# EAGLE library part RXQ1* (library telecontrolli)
RXQ1-433.9 Dual Band FM Transceiver Source: http://www.telecontrolli.com/pdf/transceivers/RXQ1.pdf
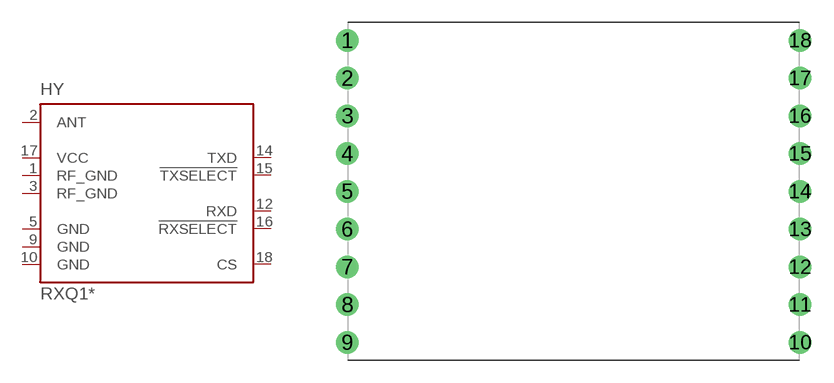
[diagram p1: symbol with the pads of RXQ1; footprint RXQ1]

Designator prefix HY

## RXQ1-433.9 (MPN: FM-RXQ1-433; OC_FARNELL: 1200988; OC_NEWARK: 96K9948)  [RXQ1]
1  RF_GND  pwr
2  ANT  in
3  RF_GND  pwr
5  GND  pwr
9  GND  pwr
10  GND  pwr
12  RXD  out
14  TXD  in
15  !TXSELECT  in
16  !RXSELECT  in
17  VCC  pwr
18  CS  in

## Footprint RXQ1 (pad centres in mm)
RXQ1-433.9 Dual Band FM Transceiver Source: http://www.telecontrolli.com/pdf/transceivers/RXQ1.pdf
drill 1 pad 1.422 round: 1 -15.24,10.16; 2 -15.24,7.62; 3 -15.24,5.08; 4 -15.24,2.54; 5 -15.24,0; 6 -15.24,-2.54; 7 -15.24,-5.08; 8 -15.24,-7.62; 9 -15.24,-10.16; 10 15.24,-10.16; 11 15.24,-7.62; 12 15.24,-5.08; 13 15.24,-2.54; 14 15.24,0; 15 15.24,2.54; 16 15.24,5.08; 17 15.24,7.62; 18 15.24,10.16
